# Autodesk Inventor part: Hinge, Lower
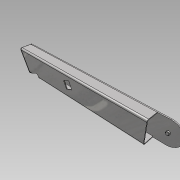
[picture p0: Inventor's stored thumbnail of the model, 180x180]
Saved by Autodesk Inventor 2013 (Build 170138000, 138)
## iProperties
Created: 2012-10
Part Number: Hinge, Lower
Material: Stainless Steel
Document SubType Name: Modeling
Designer: VMuser
Density: 8.08 g/cm^3
Mass: 3364.13 g
Surface Area: 2466.83 cm^2
Volume: 416.352 cm^3
Author: VMuser
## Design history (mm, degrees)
derived "Hinge, Lower.iam"
body "Solid1"
node "glass sheet.ipt:1"
node "Glass section.ipt:1"
node "glass holder.ipt:1"
node "Hinge 1.ipt:1"
node "PK46.51.13.004.ipt:1"
node "PK46.51.13.004.ipt:2"
